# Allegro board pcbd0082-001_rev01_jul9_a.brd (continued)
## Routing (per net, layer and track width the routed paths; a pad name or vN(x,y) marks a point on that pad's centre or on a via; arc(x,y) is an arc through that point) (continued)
MUX_NFP_PCIE0_WAKE_L: length 53
  TOP w0.132: U1.AE28 v2(45.9,49.28)
  TOP w0.147: U20.13 25.26,56.53 25.01,56.79 24.63,56.79 24.37,57.05 24.37,57.33 R384.2
  07_SIG w0.121: v2(45.9,49.28) 46.42,49.81 54.98,49.81 55.36,50.19 55.36,53.39 55.07,53.69 52.75,53.69 50.41,56.03 50.41,56.78 50.1,57.09 50.1,58.63 49.01,59.71 41.9,59.71 39.87,57.68 35.04,57.68 v7(34.15,56.79)
  08_SIG w0.121: v4(24.12,57.43) 24.63,56.92 27.8,56.92 28.57,57.69 33.25,57.69 v7(34.15,56.79)
MUX_NFP_SMBUS_ALERT_L: length 34.5
  TOP w0.132: U1.AD30 v2(43.9,48.28)
  TOP w0.147: U20.3 24.75,53.68 24.75,53.11 24.63,52.98 24.37,52.98 24.27,52.88 R381.2
  04_SIG w0.121: v8(43.9,56.28) 43.3,55.69 41.73,55.69 41.31,55.27 41.24,55.27 41.17,55.19 34.19,55.19 32.02,53.02 29.81,53.02 29.17,53.67 28.73,53.67 28.24,53.18 27.87,53.18 27.38,53.67 25.18,53.67 24.24,52.72 24.24,52.65 24.12,52.53 v4(24.12,52.47)
  08_SIG w0.121: v2(43.9,48.28) 43.9,48.89 44.7,49.69 44.95,49.69 45.3,50.04 45.3,52.31 44.5,53.12 44.5,53.26 44.07,53.69 43.86,53.69 43.42,54.13 43.42,55.78 43.9,56.25 v8(43.9,56.28)
MUX_NFP_SMBUS_SCL: length 51.8
  TOP w0.132: U1.AD29 v2(44.9,48.28)
  TOP w0.147: R383.2 26.76,57.07 U20.10
  03_SIG w0.121: v4(26.28,57.43) 26.75,57.93 45.11,57.93 45.24,58.06 50.47,58.06 v5(50.6,57.93)
  07_SIG w0.121: v2(44.9,48.28) 45.41,48.79 55.99,48.79 56.38,49.17 56.38,53.62 56.11,53.88 55.61,53.88 55.3,54.19 55.3,54.45 55.07,54.69 54.93,54.69 54.72,54.89 54.72,55.52 54.47,55.78 51.8,55.78 50.6,56.98 v5(50.6,57.93)
MUX_NFP_SMBUS_SDA: length 30.3
  TOP w0.132: U1.AE29 v2(44.9,49.28)
  TOP w0.147: v4(26.25,52.47) 26.26,52.49 U20.6
  04_SIG w0.121: v8(44.9,55.28) 44.38,54.76 41.52,54.76 41.39,54.89 40.96,54.89 40.94,54.9 37.9,54.9 37.89,54.89 37.07,54.89 36.94,54.76 34.11,54.76 32.13,52.77 31.66,52.77 31.38,52.5 28.92,52.5 28.49,52.93 27.77,52.93 27.71,52.98 26.76,52.98 v4(26.25,52.47)
  08_SIG w0.121: v8(44.9,55.28) 44.9,55.22 44.44,54.76 44.44,54.17 44.93,53.69 45.07,53.69 45.5,53.26 45.5,53.12 45.73,52.88 45.87,52.88 46.34,52.41 46.34,50.16 45.87,49.69 45.58,49.69 45.18,49.28 v2(44.9,49.28)
NFP_ARM_SPI_FLASH_MISO: length 41.9
  TOP w0.132: U1.P29 v2(44.9,37.28)
  TOP w0.147: v1(29.07,43.84) 28.6,43.37 28.6,43.04 28.13,42.57 28.13,41.2 27.93,41 27.93,39.14 27.17,38.38 26.02,38.38 v5(25.13,37.49) 24.68,37.03 U15.2
  07_SIG w0.121: v2(44.9,37.28) 44.44,37.74 44.44,38.5 44.18,38.76 43.68,38.76 43.42,39.01 43.42,39.27 43.3,39.39 43.3,39.45 43.07,39.69 41.43,39.69 40.76,39.02 40.17,39.02 40.16,39.01 33.39,39.01 33.07,38.7 33.07,38.44 32.75,38.12 31.64,38.12 31.34,37.82 31.34,37.56 31.11,37.33 29.87,37.33 29.71,37.49 28.69,37.49 27.8,36.6 26.53,36.6 25.64,37.49 v5(25.13,37.49)
  BOTTOM w0.147: v5(25.13,37.49) 25.13,40.58 25.26,40.71 25.26,41.39 R20.2
NFP_ARM_SPI_FLASH_MOSI: length 24.4
  TOP w0.147: U15.5 v4(27.22,40.66) 27.37,40.95 27.67,41.25 R23.2
  04_SIG w0.121: v3(40.72,40.41) 39.48,40.41 38.98,39.9 37.07,39.9 36.56,39.39 35.8,39.39 35.17,40.03 32.88,40.03 32.12,40.79 27.34,40.79 27.22,40.67 v4(27.22,40.66)
  BOTTOM w0.147: U7.5 27.67,36.35 27.04,36.98 27.04,40.52 27.19,40.66 v4(27.22,40.66) 27.22,40.71 v1(27.8,41.3)
NFP_ARM_SPI_FLASH_SCK: length 29.6
  TOP w0.147: U15.6 v4(25.95,40.66) 26.4,41.12 R22.2
  04_SIG w0.121: v4(25.95,40.66) 26.83,39.77 31.1,39.77 31.36,39.52 34.91,39.52 35.51,38.92 38.6,38.92 39.01,38.51 39.01,37.71 39.36,37.36 39.83,37.36 v3(40.33,36.85)
  BOTTOM w0.147: v4(25.95,40.66) 25.77,40.49 25.77,36.6 26.4,35.96 26.4,32.32 27.03,31.7 27.62,31.7 28.51,30.81 v1(28.55,30.81)
NFP_ARM_SPI_FLASH_SEL: length 46.1
  TOP w0.147: v1(21.32,36.47) 21.83,36.47 22.09,36.22 22.09,33.57 22.23,33.42 23.1,33.42 23.41,33.12 U15.1 23.41,32.1 23.86,31.65 v4(23.86,31.1)
  04_SIG w0.121: v2(41.9,42.28) 41.93,42.28 42.5,41.72 42.5,38.85 41.89,38.24 41.76,38.24 40.87,37.35 40.17,37.35 39.48,38.04 39.48,38.63 38.98,39.14 38.7,39.14 38.7,39.15 35.67,39.15 35.04,39.77 31.74,39.77 31.1,40.41 27.67,40.41 27.42,40.16 27.08,40.16 26.04,41.19 25.79,41.19 25.13,40.54 25.13,40.28 24.63,39.77 24.63,38.25 v5(23.86,37.49)
  BOTTOM w0.147: R32.1 v5(23.86,37.49) 23.86,36.6 24.5,35.96 24.5,31.27 24.37,31.14 23.9,31.14 v4(23.86,31.1)
NFP_ARM_SPI_FLASH_WP_L: length 35
  TOP w0.132: U1.AA29 v8(44.9,45.28)
  TOP w0.147: v5(26.4,37.49) 25.95,37.03 U15.3
  03_SIG w0.121: v8(44.9,45.28) 44.21,45.28 43.3,46.19 43.3,46.45 42.99,46.76 42.66,46.76 42.3,46.4 42.3,46.02 42.02,45.74 38.89,45.74 37.58,47.05 34.95,47.05 33.01,45.11 33.01,43.71 32.5,43.2 31.99,43.2 26.4,37.62 v5(26.4,37.49)
  BOTTOM w0.147: R29.2 v5(26.4,37.49)
NFP_CFG_SPI_FLASH_HOLD_L: length 68.2
  TOP w0.147: v3(33.06,34.36) 32.65,34.78 U2.K12
  07_SIG w0.121: v4(27.29,14.06) 27.63,14.39 27.63,14.64 28.17,15.18 29.33,15.18 30.66,13.85 30.66,13.62 30.92,13.36 32.45,13.36 32.75,13.06 33.86,13.06 34.35,13.55 34.71,13.55 35.13,13.13 37.49,13.13 37.88,12.74 38.38,12.74 38.98,12.15 40.43,12.15 41.31,11.27 42.42,11.27 42.8,11.65 44.24,11.65 44.5,11.91 44.5,13.55 v4(44.06,13.99)
  08_SIG w0.121: v4(27.29,14.06) 27.17,14.18 27.17,17.99 30.03,20.85 30.03,21.56 29.9,21.69 29.9,22.05 30.03,22.18 30.03,25.24 31.92,27.14 31.92,27.77 33,28.84 33,29.24 33.01,29.25 33.01,32.54 32.63,32.92 32.63,33.81 33.06,34.24 v3(33.06,34.36) 32.7,34.36 32.37,34.69 32.37,36.85 33.02,37.5 33.02,37.88 32.73,38.16 32.46,38.16 32.23,38.39 32.23,38.77 29.71,41.3 29.71,45.74 28.94,46.51 28.31,46.51 27.8,46 27.29,46 26.66,46.63 26.66,46.89 25.39,48.16 v4(25.39,49.55)
  BOTTOM w0.147: R25.2 v4(25.39,49.55)
NFP_CFG_SPI_FLASH_MISO: length 26.2
  TOP w0.132: U1.V30 v2(43.9,42.28)
  TOP w0.147: U8.2 25.39,43.84 v7(25.77,43.46)
  04_SIG w0.121: v2(43.9,42.28) 43.3,42.88 40.94,42.88 40.56,43.26 40.56,43.26 40.3,43.52 40.3,43.52 40.17,43.65 39.94,43.65 39.68,43.91 39.68,45.04 37.58,47.14 34.79,47.14 31.74,44.09 26.4,44.09 v7(25.77,43.46)
  BOTTOM w0.147: v7(25.77,43.46) 25.77,44.09 25.51,44.35 R24.2
NFP_CFG_SPI_FLASH_MOSI: length 30.6
  04_SIG w0.121: v3(40.33,39.52) 40.87,39.52 40.99,39.64 40.99,39.66 41.39,40.05 41.39,40.68 40.99,41.07 39.13,41.07 38.6,40.54 36.55,40.54 36.49,40.6 36.13,40.6 36.07,40.54 33.52,40.54 32.5,41.55 27.17,41.55 26.78,41.93 26.18,41.93 24.94,43.17 24.94,43.78 24.5,44.22 24.5,46.36 24.38,46.47 24.38,47.3 24.97,47.89 24.99,47.89 26.02,48.92 26.02,49.68 26.4,50.06 27.42,50.06 v4(27.93,49.55)
  BOTTOM w0.147: R27.2 v4(27.93,49.55)
NFP_CFG_SPI_FLASH_SCK: length 30
  04_SIG w0.121: v4(26.66,49.55) 26.66,48.66 25.38,47.39 25.18,47.39 24.89,47.09 24.89,46.68 25.01,46.56 25.01,45.87 25.26,45.62 25.26,43.33 25.77,42.82 32.75,42.82 34.54,41.04 35.5,41.04 35.61,40.93 37.01,40.93 37.12,41.04 37.93,41.04 37.96,41.04 38.6,41.68 41.01,41.68 41.11,41.58 41.2,41.58 41.48,41.29 41.48,41.11 41.64,40.96 41.64,39.59 41.5,39.45 41.5,39.3 41.37,39.17 41.37,38.78 v3(40.33,37.74)
  BOTTOM w0.147: R26.2 v4(26.66,49.55)
NFP_CFG_SPI_FLASH_SEL: length 28.5
  TOP w0.147: U8.1 24.12,43.84 v5(24.5,43.46) 24.24,43.2 v1(22.72,43.2)
  04_SIG w0.121: v3(40.33,38.63) 39.87,39.1 39.87,39.77 40,39.91 40.81,39.91 41.13,40.24 41.13,40.58 40.89,40.83 39.52,40.83 38.85,40.16 36.94,40.16 36.5,39.71 35.83,39.71 35.27,40.28 33.27,40.28 32.37,41.17 26.94,41.17 26.56,41.55 25.31,41.55 24.5,42.36 v5(24.5,43.46)
  BOTTOM w0.147: v5(24.5,43.46) R30.2 R18.1
NFP_CFG_SPI_FLASH_WP_L: length 23.7
  TOP w0.127: v3(29.27,34.49) 29.72,34.91 30.26,34.91 30.39,34.78 U2.K14
  TOP w0.147: v7(27.93,43.33) 27.04,43.33 26.66,43.71 U8.3
  07_SIG w0.121: v7(27.93,43.33) 28.18,43.08 28.18,41 25.93,38.76 24.5,38.76 23.36,37.62 23.36,37.23 26.1,34.49 v3(29.27,34.49)
  BOTTOM w0.147: R31.2 26.66,43.71 27.04,43.33 v7(27.93,43.33)
NFP_CLK_NRESET_L: length 19.8
  TOP w0.132: U1.M28 v2(45.9,35.28)
  TOP w0.147: v3(29.2,37.02) v1(29.2,37.87)
  07_SIG w0.121: v3(29.2,37.02) 29.49,36.73 31.99,36.73 32.75,35.96 38.72,35.96 39.22,35.47 41.02,35.47 41.39,35.84 43.04,35.84 43.5,35.38 43.5,35.12 43.79,34.82 45.44,34.82 v2(45.9,35.28)
NFP_CLK_NRESET_OUT_L: length 6.9
  TOP w0.127: v3(40.25,34.95) 39.7,34.4 38.42,34.4 38.3,34.28 U2.J1
  TOP w0.132: U1.M31 v2(42.9,35.28)
  07_SIG w0.121: v2(42.9,35.28) 42.44,34.82 40.37,34.82 v3(40.25,34.95)
  BOTTOM w0.147: R19.2 43.4,34.78 v2(42.9,35.28)
NFP_CLK_REF_N: length 25.1
  TOP w0.099: U1.T27 v2(46.9,39.28) ; R135.2 v7(40.25,49.05)
  03_SIG w0.096: v7(40.25,49.05) 40.25,49.45 40.54,49.74 41.19,49.74 41.25,49.67 41.65,49.67 42.06,49.67 42.06,49.67 42.42,49.67 43.41,48.67 44.06,48.67 44.29,48.44 44.29,47.92 44.53,47.67 47.06,47.67 47.29,47.44 47.29,46.44 47.29,46.44 47.29,46.03 47.65,45.67 48.06,45.67 48.29,45.44 48.29,45.03 48.65,44.68 49.5,44.68 50.29,43.89 50.29,39.12 50.06,38.89 47,38.89 46.9,38.99 v2(46.9,39.28)
  BOTTOM w0.099: v2(46.9,39.28) U1.T27
NFP_CLK_REF_P: length 25.2
  TOP w0.099: R134.2 v7(40.25,50.19) ; U1.R27 v2(46.9,38.28)
  03_SIG w0.096: v2(46.9,38.28) 47.29,38.68 50.15,38.68 50.5,39.03 50.5,43.98 49.59,44.89 48.74,44.89 48.51,45.12 48.51,45.53 48.15,45.89 47.74,45.89 47.51,46.12 47.51,46.53 47.5,46.53 47.5,47.53 47.15,47.89 44.62,47.89 44.5,48.01 44.5,48.53 44.15,48.89 43.5,48.89 42.5,49.89 42.15,49.89 41.34,49.89 41.28,49.95 41.17,49.95 41.13,50 40.44,50 v7(40.25,50.19)
  BOTTOM w0.099: v2(46.9,38.28) U1.R27
NFP_CORE_PWM1: length 44.2
  TOP w0.147: U10.29 37.66,22.47 38.21,23.03 v7(38.21,23.01)
  07_SIG w0.121: v5(67.86,21.11) 68.1,20.87 70.49,20.87 71.23,21.61 71.23,22.38 71.36,22.5 71.36,25.55 71.11,25.8 47.61,25.8 46.22,24.41 45.2,24.41 44.44,23.65 42.91,23.65 42.66,23.39 38.6,23.39 v7(38.21,23.01)
  BOTTOM w0.203: U6.40 68.03,20.98 67.91,21.11 v5(67.86,21.11)
NFP_CORE_PWM2: length 15.4
  TOP w0.147: U10.28 37.69,21.97 37.71,21.99 v7(38.07,21.99)
  04_SIG w0.121: v5(48.26,21.11) 47.12,19.96 46.09,19.96 45.45,20.6 43.93,20.6 43.6,20.27 39.03,20.27 38.72,19.96 37.83,19.96 37.58,20.22 37.58,20.99 38.07,21.49 v7(38.07,21.99)
  BOTTOM w0.203: U5.40 48.44,20.98 48.31,21.11 v5(48.26,21.11)
NFP_CORE_VID0: length 54.3
  TOP w0.132: U1.AJ31 v8(42.9,53.28)
  08_SIG w0.121: v8(42.9,53.28) 42.41,53.78 42.41,54.38 42.15,54.63 42.12,54.63 42.07,54.69 40.56,54.69 38.98,53.1 38.46,53.1 37.96,52.6 37.96,52.08 37.59,51.71 37.59,51.66 34.15,48.22 32.31,48.22 31.61,48.92 31,48.92 30.05,47.97 27.35,47.97 26.22,49.11 26.22,50 25.7,50.51 24.94,50.51 24.56,50.12 24.56,46.06 25.01,45.62 25.01,42.85 24.63,42.47 24.63,41.55 25.13,41.04 25.13,40.66 27.57,38.22 30.25,38.22 30.48,37.99 30.48,37.35 31.37,36.46 31.37,28.99 31.34,28.97 31.34,28.92 29.75,27.33 v5(29.71,27.33)
  BOTTOM w0.147: v5(29.71,27.33) R179.1
NFP_CORE_VID1: length 54.2
  TOP w0.132: U1.AG31 v8(42.9,51.28)
  08_SIG w0.121: v5(31.48,27.33) 31.48,28.09 32.15,28.76 32.15,29.45 31.61,30 31.61,36.6 31.36,36.85 31.36,37.95 30.8,38.5 27.8,38.5 26.4,39.9 26.4,41.04 25.64,41.81 25.64,42.57 25.33,42.88 25.33,43.64 25.39,43.7 25.39,46.25 24.95,46.69 24.95,49.87 25.13,50.06 25.5,50.06 25.9,49.67 25.9,48.79 27.42,47.27 27.68,47.27 28,46.95 28.5,46.95 29.2,47.65 29.64,47.65 29.71,47.72 30.16,47.72 30.34,47.9 34.66,47.9 36.06,49.3 36.06,49.43 38.6,51.97 39.1,51.97 40.88,53.74 42.01,53.74 42.41,53.35 42.41,53.11 42.66,52.86 42.9,52.86 43.3,52.45 43.3,51.69 v8(42.9,51.28)
  BOTTOM w0.147: R176.1 v5(31.48,27.33)
NFP_CORE_VID2: length 35.7
  TOP w0.132: U1.AH32 v2(41.9,52.28)
  08_SIG w0.121: v6(33.26,27.58) 33.26,28.34 33.78,28.86 33.78,29.37 34.92,30.51 34.92,33.03 34.74,33.21 34.52,33.21 34.26,33.47 34.26,34.53 34,34.79 33.71,34.79 33.45,35.04 33.45,36.15 34.72,37.43 34.72,38.95 31.99,41.68 31.99,44.73 37.96,50.7 38.98,50.7 39.23,50.95 39.23,51.33 39.93,52.03 41.65,52.03 v2(41.9,52.28)
  BOTTOM w0.147: v6(33.26,27.58) 32.83,27.15 32.83,27.06 R172.1
NFP_CORE_VID3: length 37.1
  TOP w0.132: U1.AJ32 v8(41.9,53.28)
  08_SIG w0.121: v5(34.15,27.33) 33.81,27.67 33.81,28.44 34.05,28.68 34.38,28.68 34.65,28.95 34.65,29.35 35.8,30.5 35.8,31.85 35.8,31.85 35.8,32.16 35.41,32.55 35.41,33.05 35.07,33.39 35.07,33.77 34.66,34.19 34.66,34.65 34.28,35.03 34.28,36.22 35.55,37.49 35.55,38.36 35.54,38.37 35.54,38.9 32.88,41.55 32.88,43.85 32.94,43.91 32.94,45.16 36.13,48.34 36.63,48.34 37.97,49.68 39.23,49.68 39.68,50.13 39.68,51.39 40.08,51.79 41.97,51.79 42.06,51.88 42.07,51.88 42.3,52.12 42.3,52.12 42.41,52.22 42.41,52.47 41.9,52.98 v8(41.9,53.28)
  BOTTOM w0.147: R175.1 v5(34.15,27.33)
NFP_CORE_VID4: length 30.4
  TOP w0.132: U1.AG32 v2(41.9,51.28)
  08_SIG w0.121: v2(41.9,51.28) 41.59,51.28 40.69,50.38 40.69,50.01 40.43,49.75 40.19,49.75 39.36,48.92 39.36,44.35 39.37,44.29 39.37,43.69 39.36,43.63 39.36,42.57 36.35,39.56 36.35,38.37 36.43,38.29 36.43,37.48 35.07,36.13 35.07,34.23 35.33,33.97 35.63,33.97 35.89,33.71 35.89,33.21 36.58,32.52 36.58,31.41 36.44,31.27 36.44,30.25 35.46,29.27 35.46,28.92 35.93,28.45 v6(35.93,27.58)
  BOTTOM w0.147: v6(35.93,27.58) 35.49,27.15 35.49,27.06 R174.1
NFP_CORE_VID5: length 30.7
  TOP w0.132: U1.AH31 v8(42.9,52.28)
  08_SIG w0.121: v5(36.82,27.33) 36.27,27.87 36.27,29.32 36.82,29.87 36.82,33.68 36.56,33.93 36.17,33.93 35.92,34.19 35.92,35.45 37.21,36.74 37.21,38.32 37.16,38.37 37.16,39.87 39.68,42.38 39.68,47.96 40.06,48.34 40.18,48.34 40.94,49.1 40.94,50.12 41.64,50.82 42.02,50.82 42.5,51.3 42.5,51.88 v8(42.9,52.28)
  BOTTOM w0.147: R177.1 v5(36.82,27.33)
NFP_CORE_VID6: length 27.2
  TOP w0.132: U1.AF32 v2(41.9,50.28)
  08_SIG w0.121: v2(41.9,50.28) 41.39,49.77 41.39,48.69 41.25,48.55 41.25,41.55 39.87,40.17 39.87,36.58 39.6,36.31 39.07,36.31 38.21,35.46 38.21,35.33 37.89,35.01 37.89,30.06 38.79,29.17 38.79,28.28 38.6,28.09 v7(38.6,27.58)
  BOTTOM w0.147: v7(38.6,27.58) 38.16,27.15 38.16,27.14 37.83,26.81 37.83,26.73 R173.1
NFP_CORE_VID7: length 31.2
  TOP w0.132: U1.AG30 v2(43.9,51.28)
  08_SIG w0.121: v2(43.9,51.28) 43.9,50.54 42.05,48.69 41.73,48.69 41.5,48.45 41.5,40.52 40.75,39.77 40.75,39.77 40.75,39.76 40.75,36.25 39.83,35.33 39.83,34.56 40.72,33.66 41.07,33.66 41.52,33.22 41.52,26.95 41.01,26.44 41.01,26.27 v4(40.28,25.55)
  BOTTOM w0.147: v4(40.28,25.55) 40.28,24.88 v1(40.88,24.28)
NFP_CPLD_INT_L: length 39.5
  TOP w0.127: U2.L14 30.94,35.75 29.69,35.75 v3(29.27,35.33)
  TOP w0.132: U1.AA28 v2(45.9,45.28)
  TOP w0.147: v1(30.47,42.82) 30.21,42.57 30.21,40.79 29.83,40.41 29.2,40.41 28.58,39.8 28.58,38.01 28.56,37.99 28.56,35.58 28.82,35.33 v3(29.27,35.33)
  03_SIG w0.105: 47.49,43.41 47.06,43.84 46.6,43.84 46.5,43.93 46.5,44.53 45.9,45.13 v2(45.9,45.28)
  03_SIG w0.121: v3(29.27,35.33) 29.27,35.91 29.96,36.6 30.34,36.6 30.59,36.85 37.41,36.85 38.46,37.91 38.76,37.91 38.99,38.13 40.39,38.13 40.73,38.47 40.73,38.68 42.71,40.66 44.95,40.66 45.5,41.21 45.5,41.45 45.73,41.69 45.97,41.69 46.5,42.21 46.5,42.45 46.73,42.69 46.97,42.69 47.49,43.2 47.49,43.41
  BOTTOM w0.127: v3(29.27,35.33) 29.69,34.91 30.26,34.91 30.35,34.82 R58.1
NFP_CPLD_PRGM_JTAG_TCK: length 38.4
  TOP w0.132: U1.AD28 v2(45.9,48.28)
  TOP w0.147: U12.3 26.52,27.85 26.4,27.96 v4(26.4,29.07)
  04_SIG w0.121: v4(26.4,29.07) 27.71,30.38 29.45,30.38 29.87,30.79 34.19,30.79 34.92,31.53 34.92,32.42 35.92,33.42 35.92,35.29 36.34,35.71 36.69,35.71 37.07,36.09 38.56,36.09 39.04,36.57 39.04,36.86 39.29,37.11 39.58,37.11 39.82,36.86 39.82,36.81 40.17,36.46 41.25,36.46 41.52,36.73 43.04,36.73 43.42,37.11 43.42,38.23 43.5,38.31 43.5,41.45 43.93,41.88 44.07,41.88 44.31,42.12 44.31,42.31 44.87,42.88 45.07,42.88 45.45,43.27 45.45,45.41 45.93,45.88 46.22,45.88 46.47,46.12 46.47,47.71 v2(45.9,48.28)
NFP_CPLD_PRGM_JTAG_TDI: length 51.1
  TOP w0.132: U1.AC27 v2(46.9,47.28)
  TOP w0.147: v4(22.63,30.38) 22.63,30.82 22.21,31.24 v1(22.21,31.77) 22.8,31.77 23.36,31.22 23.36,30.97 23.66,30.66 23.66,28.67 24.37,27.96 24.75,27.96 25.02,27.7 U12.6
  04_SIG w0.121: v2(46.9,47.28) 47.36,46.82 47.36,43.08 46.97,42.69 46.73,42.69 46.5,42.45 46.5,42.31 46.07,41.88 45.93,41.88 45.45,41.41 45.45,35.2 45.07,34.82 41.77,34.82 41.26,35.33 41.26,35.34 41.14,35.46 39.58,35.46 39.57,35.47 38.43,35.47 38.42,35.46 37.45,35.46 37.07,35.08 37.07,31.77 34.79,29.49 29.83,29.49 28.94,28.6 23.74,28.6 23.48,28.85 23.48,29.53 v4(22.63,30.38)
NFP_CPLD_PRGM_JTAG_TDO: length 48.9
  TOP w0.132: U1.AC28 v2(45.9,47.28)
  TOP w0.147: R67.2 v4(24.27,23.58) 24.52,23.83 U12.10
  03_SIG w0.121: v2(45.9,47.28) 46.34,46.84 46.34,46.25 46.91,45.69 47.07,45.69 47.3,45.45 47.3,45.29 47.91,44.69 48.07,44.69 48.3,44.45 48.3,44.29 48.88,43.71 49.14,43.71 49.39,43.46 49.39,43.2 49.07,42.88 48.73,42.88 48.3,42.45 48.3,42.12 48.07,41.88 47.73,41.88 47.3,41.45 47.3,41.12 47.07,40.88 46.73,40.88 45.67,39.81 43.84,39.81 43.3,39.28 43.3,39.12 42.87,38.69 42.73,38.69 41.5,37.45 41.5,37.34 40.43,36.28 38.28,36.28 38.09,36.09 31.46,36.09 30.25,34.88 29.92,34.88 29.66,34.62 29.66,34.33 29.44,34.1 28.27,34.1 v5(27.04,35.33)
  08_SIG w0.121: v4(24.27,23.58) 24.24,24.41 23.86,24.79 23.86,28.34 23.61,28.6 23.61,29.23 23.87,29.49 24.3,29.49 25.26,30.45 25.26,30.66 26.02,31.42 26.02,34.31 v5(27.04,35.33)
NFP_CPLD_PRGM_JTAG_TMS: length 48.7
  TOP w0.132: U1.AC30 v2(43.9,47.28)
  TOP w0.147: R66.2 26.44,24.03 26.28,24.03 26.02,24.28 U12.13
  03_SIG w0.121: v7(28.18,32.03) 28.18,32.15 26.6,33.74 26.6,35.51 26.86,35.77 27.87,35.77 28.75,34.88 29.39,34.88 29.69,35.19 29.69,35.49 29.92,35.72 30.22,35.72 30.98,36.47 37.71,36.47 38.34,37.11 40.04,37.11 40.17,37.25 40.51,37.25 42.41,39.14 42.41,39.52 43.17,40.28 45.58,40.28 46.5,41.2 46.5,41.45 46.73,41.69 46.98,41.69 47.5,42.2 47.5,42.45 47.73,42.69 47.98,42.69 48.37,43.08 48.37,43.46 47.95,43.88 47.73,43.88 47.5,44.12 47.5,44.26 47.07,44.69 46.93,44.69 46.5,45.12 46.5,45.26 46.01,45.74 45.71,45.74 45.45,46 45.45,46.51 45.2,46.76 44.42,46.76 v2(43.9,47.28)
  07_SIG w0.121: v4(26.91,23.58) 26.91,29.84 27.03,29.96 28.18,31.11 v7(28.18,32.03)
NFP_FAIL_SAFE_BOOT_L: length 84.7
  TOP w0.127: v3(33.87,34.36) 33.45,34.78 33.45,35.35 33.41,35.39 U2.M10
  TOP w0.132: U1.AB30 v2(43.9,46.28)
  TOP w0.147: v5(22.34,32.79) 22.12,32.57 R34.1
  07_SIG w0.121: v2(43.9,46.28) 43.42,46.76 37.96,46.76 37.58,47.14 34.66,47.14 31.23,43.71 31.23,42.82 26.46,38.05 25.08,38.05 24.69,37.67 24.69,37.1 24.81,36.98 25.51,36.98 26.66,35.84 27.15,35.84 27.27,35.72 30.25,35.72 30.39,35.58 34.83,35.58 35.07,35.34 35.07,35.04 35.36,34.76 35.66,34.76 35.89,34.53 35.89,34.2 35.63,33.94 34.9,33.94 34.48,34.36 v3(33.87,34.36) 33.61,34.36 33.22,33.97 32.9,33.97 32.82,34.05 28.8,34.05 27.42,32.66 22.47,32.66 v5(22.34,32.79)
  08_SIG w0.121: v5(22.34,32.79) 22.09,32.54 22.09,29.74 22.19,29.64 22.19,23.92 23.8,22.32 23.8,22.26 23.86,22.2 23.86,21.79 23.56,21.49 23.11,21.49 20.94,19.33 20.94,16.28 20.31,15.64 20.31,12.09 20.94,11.45 v4(20.94,10.12)
  BOTTOM w0.102: TP17.1 32.52,33.96 33.46,33.96 v3(33.87,34.36)
  BOTTOM w0.147: v2(43.9,46.28) R16.1
NFP_JTAG_ARM_TCK: length 75.3
  TOP w0.132: U1.AA31 v2(42.9,45.28)
  07_SIG w0.121: v7(44.06,15.26) 45.2,14.12 45.2,11.9 44.45,11.15 43.01,11.15 42.57,10.7 40.68,10.7 40.36,11.02 40.26,11.13 39.2,11.13 38.99,11.34 37.85,11.34 37.13,12.06 36.47,12.06 v4(36.44,12.09) 36.43,12.09 36.39,12.13 35.59,12.13 35.37,11.91 32.49,11.91 32.04,12.37 29.76,12.37 28.77,13.36 28.36,13.36 28.06,13.06 28.06,12.7 26.67,11.31 25.42,11.31 25.14,11.03 16.47,11.03 v4(14.59,12.91)
  08_SIG w0.121: v7(44.06,15.26) 43.8,15.52 43.8,21.11 44.44,21.74 44.44,30.74 v2(43.9,31.28) 44.44,31.77 44.44,39.9 45.45,40.92 45.45,43.3 45.07,43.69 44.93,43.69 44.5,44.12 44.5,44.29 43.5,45.28 v2(42.9,45.28)
  BOTTOM w0.147: v4(14.59,12.91) 14.66,12.98 14.97,12.98 15.86,13.87 J5.5 ; R408.1 43.9,30.51 v2(43.9,31.28)
NFP_JTAG_ARM_TDI: length 86.1
  TOP w0.132: U1.Y32 v2(41.9,44.28)
  04_SIG w0.121: v5(28.18,47.39) 30.09,45.49 32.28,45.49 34.5,47.71 34.59,47.71 35.17,48.29 36.07,48.29 36.13,48.34 36.49,48.34 36.55,48.29 37.13,48.29 40.17,45.25 40.17,45.15 40.97,44.35 41.38,44.35 41.45,44.28 v2(41.9,44.28)
  07_SIG w0.121: v4(38.34,12.09) 37.94,12.49 37.78,12.49 37.39,12.88 35.28,12.88 35.06,12.66 32.8,12.66 32.35,13.11 30.82,13.11 30.31,13.62 29.65,13.62 29.25,14.01 29.25,14.53 28.85,14.94 28.28,14.94 27.87,14.53 27.87,13.99 27.31,13.43 27.31,13.01 26.36,12.06 25.11,12.06 24.89,11.83 22.09,11.83 22.05,11.82 21.87,11.78 18.38,11.78 17.89,12.27 17.89,12.78 17.31,13.36 16.3,13.36 v4(15.86,12.91)
  08_SIG w0.121: v4(38.34,12.09) 39.03,12.78 39.03,13.9 38.85,14.08 38.85,14.12 38.47,14.5 38.47,15.97 38.53,16.03 38.53,16.4 38.47,16.46 38.47,17.68 40.05,19.25 40.09,19.25 40.34,19.51 40.34,19.55 40.83,20.04 40.83,23.32 40.5,23.65 40.5,24.92 40.83,25.24 40.83,25.57 41.39,26.13 41.39,26.44 41.77,26.82 41.77,33.33 41.64,33.46 41.64,33.58 41.31,33.91 40.83,33.91 40.57,34.17 40.57,34.53 40.88,34.85 40.88,34.88 40.99,34.99 40.99,39.66 41.31,39.97 41.31,39.98 41.74,40.41 41.74,40.51 42.41,41.17 42.41,43.46 41.9,43.96 v2(41.9,44.28)
  BOTTOM w0.147: J5.7 17.13,13.87 16.24,12.98 15.93,12.98 v4(15.86,12.91) ; R403.2 27.46,47.39 v5(28.18,47.39) 29.1,47.39 R147.1
NFP_JTAG_ARM_TDO: length 83
  TOP w0.147: v5(28.69,44.73) 28.82,44.85 R263.2
  07_SIG w0.121: v5(28.69,44.73) 28.69,44.6 27.86,43.77 27.74,43.77 27.04,43.07 27.04,41.3 26.66,40.92 26.66,40.16 25.64,39.14 24.37,39.14 23.52,38.29 23.52,38.17 23.03,37.69 23.03,36.29 23.36,35.96 23.36,34.44 23.16,34.25 23.16,34 22.9,33.75 21.9,33.75 20.94,32.79 20.94,31.39 19.04,29.49 v5(14.72,29.49) ; v4(17.13,12.91) 17.13,12.68 18.28,11.53 24.94,11.53 25.22,11.81 26.47,11.81 27.56,12.91 27.56,13.33 28.12,13.89 28.12,14.43 28.38,14.69 28.74,14.69 29,14.43 29,13.91 29.55,13.37 30.21,13.37 30.71,12.87 32.24,12.87 32.69,12.42 35.17,12.42 35.38,12.63 37.17,12.63 38.16,11.65 38.52,11.65 38.58,11.71 v4(40.25,11.71)
  08_SIG w0.121: v4(17.13,12.91) 12.94,17.11 12.94,21.23 13.45,21.74 13.45,26.19 14.34,27.07 14.34,29.11 v5(14.72,29.49)
  BOTTOM w0.147: v5(28.69,44.73) 29.2,45.24 R147.2 29.95,46.65 30.39,47.09 30.39,48.68 30.59,48.88 30.59,50.06 30.34,50.32 R404.2 ; v4(17.13,12.91) 17.32,13.1 17.64,13.1 18.4,13.87 J5.9
NFP_JTAG_ARM_TMS: length 74.5
  TOP w0.132: U1.AA32 v2(41.9,45.28)
  07_SIG w0.121: v4(42.15,11.71) 41.37,12.49 39.38,12.49 38.7,13.17 38.16,13.17 37.15,14.18 34.95,14.18 34.81,14.05 34.14,14.05 34.02,13.93 31.76,13.93 30,15.69 27.97,15.69 27.12,14.84 27.12,14.6 26.79,14.27 26.79,13.85 25.5,12.56 25.02,12.56 24.8,12.34 21.99,12.34 21.98,12.33 21.9,12.3 21.82,12.28 18.59,12.28 18.4,12.47 v4(18.4,12.91)
  08_SIG w0.121: v2(41.9,45.28) 41.98,45.28 42.41,44.85 42.41,44.09 42.81,43.69 43.07,43.69 43.3,43.45 43.3,41.12 42.16,39.97 42.02,39.97 41.5,39.45 41.5,35.1 42.15,34.44 42.15,28.73 42.53,28.34 42.53,26.19 42.15,25.8 41.77,25.8 41.33,25.36 41.33,16.9 41.9,16.33 41.9,11.96 v4(42.15,11.71)
  BOTTOM w0.147: J5.11 19.67,13.61 19.16,13.1 18.59,13.1 v4(18.4,12.91) ; R405.2 42.69,49.48 42.65,49.48 42.41,49.72 41.69,49.72 41.39,49.43 41.39,45.79 v2(41.9,45.28)
NFP_JTAG_ARM_TRST_L: length 67.2
  TOP w0.132: U1.Y31 v2(42.9,44.28)
  07_SIG w0.121: v4(22.21,12.91) 22.66,13.36 25.95,13.36 26.53,13.94 26.53,14.95 27.76,16.19 30.21,16.19 31.96,14.43 33.81,14.43 33.93,14.55 34.04,14.55 35.24,15.74 35.6,15.74 36.09,15.26 36.88,15.26 38.01,14.13 38.45,14.13 39.59,12.99 43.15,12.99 v4(44.06,12.09)
  08_SIG w0.121: v4(44.06,12.09) 42.41,13.74 42.41,25.42 43.04,26.06 43.04,28.47 42.66,28.85 42.66,28.95 42.5,29.12 42.5,29.45 42.66,29.61 42.66,31.04 v2(42.9,31.28) 42.66,31.52 42.66,32.95 42.5,33.12 42.5,39.61 43.76,40.88 44.07,40.88 44.44,41.25 44.44,43.46 44.06,43.84 43.55,43.84 43.1,44.28 v2(42.9,44.28)
  BOTTOM w0.147: R406.2 43.4,31.78 v2(42.9,31.28) R407.1 ; v4(22.21,12.91) 21.89,12.91 20.94,13.87 J5.13
NFP_PCIE0_PER0_N: length 93.3
  04_SIG w0.11: v4(66.38,58.48) 66.28,58.58 66.28,59.12 64.47,60.94 49.3,60.94 48.79,60.43 34.21,60.43 33.71,60.94 17.47,60.94 17.43,60.91 9.57,60.91 7.01,58.35 7.01,56.18 7.57,55.62 7.57,46.19 9.01,44.75 9.01,41.25 10.57,39.69 16.27,39.69 16.73,40.15 16.73,43.13 16.84,43.25 17.13,43.25 17.28,43.09 v6(17.28,42.99)
  BOTTOM w0.139: J4.83 v6(17.28,42.99)
NFP_PCIE0_PER0_P: length 93.2
  04_SIG w0.11: v4(65.38,58.48) 65.68,58.48 66.07,58.87 66.07,59.04 64.38,60.73 49.39,60.73 48.88,60.22 34.13,60.22 33.62,60.73 17.56,60.73 17.52,60.69 9.66,60.69 7.23,58.26 7.23,56.27 7.78,55.71 7.78,46.28 9.22,44.84 9.22,41.33 10.66,39.9 16.18,39.9 16.52,40.24 16.52,43.22 16.75,43.46 17.13,43.46 17.28,43.61 v13(17.28,44.26)
  BOTTOM w0.139: J4.75 v13(17.28,44.26)
NFP_PCIE0_PER1_N: length 83.4
  04_SIG w0.11: v6(16.01,40.45) 15.82,40.64 15.56,40.64 15.27,40.93 15.27,41.89 14.97,42.19 10.66,42.19 10.02,42.82 10.02,45.06 8.94,46.15 8.94,46.64 8.27,47.3 8.27,56.11 8.35,56.18 8.35,56.75 8.61,57.01 8.61,58.84 9.96,60.19 17.14,60.19 17.39,59.94 28.1,59.94 28.38,60.23 33.41,60.23 33.93,59.71 49.14,59.71 49.77,60.35 63.02,60.35 64.16,59.21 64.16,58.69 v4(64.38,58.48)
  BOTTOM w0.139: J4.100 v6(16.01,40.45)
NFP_PCIE0_PER1_P: length 83.3
  04_SIG w0.11: v4(63.49,58.48) 63.78,58.48 63.95,58.66 63.95,59.12 62.94,60.14 49.86,60.14 49.22,59.5 33.84,59.5 33.33,60.01 28.47,60.01 28.18,59.73 17.31,59.73 17.05,59.98 10.04,59.98 8.82,58.75 8.82,56.92 8.56,56.66 8.56,56.1 8.48,56.02 8.48,47.39 9.15,46.73 9.15,46.23 10.23,45.15 10.23,42.91 10.74,42.4 15.06,42.4 15.48,41.98 15.48,41.02 15.65,40.85 15.79,40.85 16.01,41.07 v13(16.01,41.72)
  BOTTOM w0.139: J4.92 v13(16.01,41.72)
NFP_PCIE0_PER2_N: length 84.2
  04_SIG w0.11: v4(61.55,58.48) 61.94,58.87 61.94,59.36 61.65,59.65 60.89,59.65 60.83,59.59 50.53,59.59 49.73,58.79 33.54,58.79 33.03,59.3 28.77,59.3 28.23,58.76 19.09,58.76 18.84,59.01 17.01,59.01 16.76,59.27 11.02,59.27 9.98,58.23 9.98,57.09 9.26,56.37 9.26,48.02 11.02,46.27 11.25,46.27 11.63,45.89 11.63,45.2 11.89,44.94 17.6,44.94 18.11,44.43 18.11,39.61 17.5,39 17.5,38.39 17.98,37.91 v6(18.55,37.91)
  BOTTOM w0.139: J4.115 v6(18.55,37.91)
NFP_PCIE0_PER2_P: length 84.2
  04_SIG w0.11: v13(17.28,37.91) 17.28,39.08 17.9,39.7 17.9,44.34 17.51,44.73 11.8,44.73 11.42,45.11 11.42,45.8 11.16,46.06 10.93,46.06 9.05,47.94 9.05,56.46 9.77,57.17 9.77,58.32 10.93,59.48 16.84,59.48 17.1,59.22 18.93,59.22 19.18,58.97 28.14,58.97 28.68,59.51 33.12,59.51 33.63,59 49.65,59 50.45,59.8 60.74,59.8 60.8,59.86 61.74,59.86 62.15,59.45 62.15,58.87 v4(62.54,58.48)
  BOTTOM w0.139: J4.107 v13(17.28,37.91)
NFP_PCIE0_PER3_N: length 87.1
  04_SIG w0.11: v6(16.01,35.37) 16.01,35.78 16.13,35.9 17.62,35.9 18.05,36.33 18.05,36.85 18.31,37.11 19.04,37.11 19.29,37.36 19.29,47.14 18.91,47.52 10.78,47.52 10.44,47.86 10.44,50.53 10.36,50.61 10.36,55.86 10.71,56.21 10.86,56.21 11.45,55.63 11.78,55.63 12.09,55.94 12.09,56.28 11.51,56.86 11.51,57.01 11.71,57.22 14.29,57.22 14.62,57.54 14.88,57.87 15.57,58.55 16.46,58.55 16.72,58.3 17.15,57.86 23.93,57.86 24.11,58.05 28.52,58.05 29.06,58.59 32.73,58.59 33.27,58.05 50.01,58.05 50.91,58.95 59.87,58.95 59.95,58.87 59.95,58.6 59.83,58.48 v4(59.55,58.48)
  BOTTOM w0.139: J4.132 v6(16.01,35.37)
NFP_PCIE0_PER3_P: length 87.1
  04_SIG w0.11: v4(60.57,58.48) 60.16,58.88 60.16,58.97 59.97,59.16 50.83,59.16 49.92,58.26 33.36,58.26 32.82,58.8 28.98,58.8 28.44,58.26 24.03,58.26 23.84,58.07 17.24,58.07 16.8,58.51 16.55,58.77 15.48,58.77 14.73,58.01 14.46,57.69 14.2,57.43 11.63,57.43 11.3,57.1 11.3,56.77 11.88,56.19 11.88,56.03 11.69,55.84 11.53,55.84 10.95,56.42 10.62,56.42 10.15,55.95 10.15,50.52 10.23,50.44 10.23,47.77 10.69,47.31 18.82,47.31 19.08,47.05 19.08,37.45 18.95,37.32 18.22,37.32 17.84,36.94 17.84,36.42 17.53,36.11 16.54,36.11 v13(16.01,36.64)
  BOTTOM w0.139: J4.124 v13(16.01,36.64)
NFP_PCIE0_PER4_N: length 82.7
  03_SIG w0.11: v6(16.01,45.53) 15.49,46.06 13.29,46.06 12.82,46.53 12.82,47.21 12.62,47.41 8.18,47.41 6,49.59 6,50.45 5.88,50.57 5.18,50.57 4.94,50.82 4.94,51.25 5.18,51.5 5.88,51.5 6,51.62 6,51.88 5.88,52 5.18,52 4.94,52.25 4.94,52.68 5.18,52.93 5.88,52.93 6,53.05 6,53.31 5.88,53.43 5.18,53.43 4.94,53.67 4.94,54.11 5.18,54.35 5.88,54.35 6,54.47 6,58.66 8.25,60.91 17.43,60.91 17.56,60.78 48.64,60.78 48.79,60.94 57.61,60.94 58.6,59.95 v4(58.6,58.48)
  BOTTOM w0.139: J4.68 v6(16.01,45.53)
NFP_PCIE0_PER4_P: length 82.6
  03_SIG w0.11: v13(16.01,46.8) 16.18,46.63 16.18,46.39 16.06,46.27 13.38,46.27 13.03,46.62 13.03,47.3 12.71,47.63 8.26,47.63 6.21,49.68 6.21,50.54 5.97,50.79 5.27,50.79 5.15,50.91 5.15,51.17 5.27,51.29 5.97,51.29 6.21,51.53 6.21,51.97 5.97,52.21 5.27,52.21 5.15,52.33 5.15,52.59 5.27,52.71 5.97,52.71 6.21,52.96 6.21,53.39 5.97,53.64 5.27,53.64 5.15,53.76 5.15,54.02 5.27,54.14 5.97,54.14 6.21,54.39 6.21,58.57 8.33,60.69 17.35,60.69 17.47,60.57 48.72,60.57 48.88,60.73 57.52,60.73 58.39,59.86 58.39,58.93 57.94,58.48 v4(57.65,58.48)
  BOTTOM w0.139: J4.60 v13(16.01,46.8)
NFP_PCIE0_PER5_N: length 80.8
  03_SIG w0.11: v4(55.65,58.48) 56.08,58.82 56.08,59.37 55.28,60.16 49.33,60.16 49.03,59.86 17.17,59.86 17.05,59.98 8.63,59.98 8.48,59.83 8.48,59.66 8.92,59.22 8.92,58.87 8.62,58.56 8.27,58.56 7.83,59.01 7.65,59.01 7.18,58.53 7.18,58.02 7.3,57.9 8.51,57.9 8.75,57.65 8.75,57.22 8.51,56.97 7.3,56.97 7.18,56.85 7.18,54.81 7.75,54.23 7.75,50.85 8.08,50.53 9.81,50.53 10.19,50.91 10.19,52.39 10.51,52.71 11.44,52.71 11.76,52.38 11.76,51.7 12.13,51.33 12.73,51.33 14,50.06 14.45,50.06 14.69,49.83 14.69,49.72 14.8,49.6 15.07,49.6 15.18,49.72 15.18,49.83 15.41,50.06 17.77,50.06 18.11,49.72 18.11,49.01 17.83,48.72 17.4,48.72 17.28,48.6 v6(17.28,48.07)
  BOTTOM w0.139: J4.51 v6(17.28,48.07)
NFP_PCIE0_PER5_P: length 80.9
  03_SIG w0.11: v13(17.28,49.34) 17.28,49.06 17.4,48.94 17.74,48.94 17.9,49.1 17.9,49.63 17.68,49.85 15.5,49.85 15.39,49.74 15.39,49.63 15.16,49.39 14.71,49.39 14.48,49.63 14.48,49.74 14.37,49.85 13.92,49.85 12.65,51.12 12.04,51.12 11.55,51.61 11.55,52.29 11.35,52.49 10.6,52.49 10.4,52.3 10.4,50.82 9.89,50.32 7.99,50.32 7.54,50.76 7.54,54.15 6.97,54.72 6.97,56.94 7.21,57.19 8.42,57.19 8.54,57.31 8.54,57.57 8.42,57.69 7.21,57.69 6.97,57.93 6.97,58.62 7.57,59.22 7.91,59.22 8.36,58.77 8.53,58.77 8.71,58.96 8.71,59.13 8.27,59.57 8.27,59.92 8.54,60.19 17.14,60.19 17.26,60.07 48.94,60.07 49.24,60.37 55.37,60.37 56.29,59.46 56.29,58.82 v4(56.63,58.48)
  BOTTOM w0.139: J4.43 v13(17.28,49.34)
NFP_PCIE0_PER6_N: length 80.9
  03_SIG w0.11: v4(53.64,58.48) 54.03,58.87 54.03,59.14 53.59,59.58 49.89,59.58 49.46,59.14 16.88,59.14 16.76,59.27 12.25,59.27 11.69,58.7 11.69,58.59 11.68,58.58 11.68,58.3 11.3,57.92 10.51,57.92 10.4,57.81 10.4,57.12 10.51,57.01 12.07,57.01 12.31,56.77 12.31,56.33 12.07,56.09 10.51,56.09 10.4,55.98 10.4,55.44 10.16,55.19 9.55,55.19 9.17,55.57 9.17,55.94 9.04,56.07 8.71,56.07 8.58,55.94 8.58,51.55 8.71,51.42 9.3,51.42 9.43,51.55 9.43,54.31 9.81,54.69 10.16,54.69 10.4,54.45 10.4,54.25 10.68,53.98 12.71,53.98 13.03,53.65 13.03,52.88 13.34,52.57 13.34,51.79 13.46,51.67 13.72,51.67 13.97,51.92 13.97,53.5 14.44,53.98 15.25,53.98 15.57,53.65 15.57,52.81 15.69,52.69 17.73,52.69 18.11,52.3 18.11,51.44 17.89,51.22 17.01,51.22 16.97,51.26 16.13,51.26 16.01,51.14 v6(16.01,50.61)
  BOTTOM w0.139: J4.36 v6(16.01,50.61)
NFP_PCIE0_PER6_P: length 80.9
  03_SIG w0.11: v13(16.01,51.88) 16.01,51.6 16.13,51.48 17.06,51.48 17.1,51.44 17.74,51.44 17.9,51.59 17.9,52.21 17.64,52.47 15.61,52.47 15.36,52.72 15.36,53.56 15.16,53.76 14.53,53.76 14.18,53.42 14.18,51.83 13.81,51.46 13.38,51.46 13.13,51.7 13.13,52.48 12.82,52.79 12.82,53.56 12.62,53.76 10.59,53.76 10.19,54.17 10.19,54.36 10.07,54.48 9.89,54.48 9.64,54.23 9.64,51.46 9.39,51.2 8.62,51.2 8.37,51.46 8.37,56.03 8.62,56.28 9.13,56.28 9.39,56.03 9.39,55.66 9.64,55.4 10.07,55.4 10.19,55.52 10.19,56.07 10.42,56.3 11.98,56.3 12.09,56.41 12.09,56.69 11.98,56.8 10.42,56.8 10.19,57.03 10.19,57.9 10.42,58.13 11.22,58.13 11.47,58.39 11.47,58.67 11.48,58.68 11.48,58.79 12.16,59.48 16.84,59.48 16.97,59.36 49.37,59.36 49.8,59.79 53.68,59.79 54.24,59.23 54.24,58.87 v4(54.63,58.48)
  BOTTOM w0.139: J4.28 v13(16.01,51.88)
NFP_PCIE0_PER7_N: length 82.7
  03_SIG w0.11: v6(17.28,53.15) 17.28,53.52 17.51,53.74 19,53.74 19.29,54.04 19.29,55.01 19.08,55.23 13.28,55.23 13.03,55.48 13.03,55.94 13.27,56.19 13.86,56.19 14.1,56.44 14.1,57.01 13.73,57.39 13.03,57.39 12.9,57.52 12.9,57.72 13.03,57.85 14.49,57.85 14.61,57.73 14.61,56.44 14.85,56.19 18.79,56.19 19.1,56.5 19.1,56.88 18.85,57.13 17.6,57.13 17.47,57.26 17.47,57.72 17.56,57.81 18.91,57.81 19.1,58.01 19.1,58.1 19.44,58.43 20.1,58.43 20.22,58.31 20.22,56.4 20.46,56.16 20.9,56.16 21.14,56.4 21.14,58.31 21.26,58.43 22.15,58.43 22.27,58.31 22.27,55.13 22.51,54.89 22.95,54.89 23.19,55.13 23.19,55.76 23.31,55.88 28.57,55.88 28.82,56.13 28.82,56.56 28.57,56.81 23.31,56.81 23.19,56.93 23.19,58.31 23.31,58.43 49.89,58.43 50.41,58.95 51.8,58.95 51.88,58.87 51.88,58.65 51.71,58.48 v4(51.42,58.48)
  BOTTOM w0.139: J4.19 v6(17.28,53.15)
NFP_PCIE0_PER7_P: length 82.7
  03_SIG w0.11: v4(52.57,58.48) 51.88,59.16 50.32,59.16 49.8,58.64 23.22,58.64 22.98,58.4 22.98,56.84 23.22,56.59 28.48,56.59 28.6,56.47 28.6,56.21 28.48,56.09 23.22,56.09 22.98,55.85 22.98,55.22 22.86,55.1 22.6,55.1 22.48,55.22 22.48,58.4 22.23,58.64 21.18,58.64 20.93,58.4 20.93,56.49 20.81,56.37 20.55,56.37 20.43,56.49 20.43,58.4 20.18,58.64 19.35,58.64 18.89,58.18 18.89,58.1 18.82,58.02 17.47,58.02 17.26,57.81 17.26,57.17 17.51,56.92 18.77,56.92 18.89,56.79 18.89,56.59 18.7,56.4 14.94,56.4 14.82,56.52 14.82,57.82 14.57,58.06 12.94,58.06 12.69,57.81 12.69,57.43 12.94,57.17 13.64,57.17 13.89,56.92 13.89,56.52 13.77,56.4 13.19,56.4 12.81,56.03 12.81,55.4 13.2,55.01 18.99,55.01 19.08,54.93 19.08,54.13 18.91,53.96 17.53,53.96 17.28,54.2 v13(17.28,54.42)
  BOTTOM w0.139: J4.11 v13(17.28,54.42)
NFP_PCIE0_PET0_N: length 53.1
  TOP w0.139: v2(62.9,51.28) U1.AG12
  03_SIG w0.106: 62.3,56.27 62.3,51.89 v2(62.9,51.28)
  03_SIG w0.11: v6(19.82,53.15) 20.35,53.68 21.17,53.68 21.66,54.17 29.11,54.17 29.88,53.4 32.07,53.4 34.35,55.68 35.35,55.68 36.13,56.46 36.16,56.46 36.26,56.56 36.63,56.56 37.03,56.96 45.03,56.96 45.54,57.47 50.14,57.47 50.33,57.28 50.81,57.28 51.41,56.69 52.18,56.69 52.55,56.32 53.25,56.32 53.61,56.69 54.2,56.69 54.49,56.4 55.39,56.4 55.68,56.69 56.1,56.69 56.5,56.28 57.33,56.28 57.73,56.69 61.88,56.69 62.3,56.27
  BOTTOM w0.139: J4.17 v6(19.82,53.15)
NFP_PCIE0_PET0_P: length 53.1
  TOP w0.139: v2(62.9,52.28) U1.AH12
  03_SIG w0.106: 62.45,56.42 62.46,56.41 62.46,56.4 62.5,56.36 62.5,52.07 62.61,51.97 62.79,51.97 62.9,52.07 v2(62.9,52.28)
  03_SIG w0.11: 62.45,56.42 61.96,56.9 57.64,56.9 57.24,56.5 56.59,56.5 56.19,56.9 55.59,56.9 55.3,56.61 54.57,56.61 54.28,56.9 53.52,56.9 53.16,56.54 52.63,56.54 52.27,56.9 51.49,56.9 50.9,57.49 50.42,57.49 50.22,57.68 45.45,57.68 44.95,57.17 37.12,57.17 36.94,57.17 36.54,56.77 36.17,56.77 36.11,56.71 36.08,56.71 35.26,55.89 34.26,55.89 31.98,53.61 29.97,53.61 29.2,54.38 21.58,54.38 21.09,53.89 20.35,53.89 v13(19.82,54.42)
  BOTTOM w0.139: J4.9 v13(19.82,54.42)
NFP_PCIE0_PET1_N: length 51.4
  TOP w0.139: v2(61.9,52.28) U1.AH13
  03_SIG w0.106: 41.52,55.68 41.54,55.68 41.54,55.68 46.15,55.68 46.5,56.03 46.5,56.53 46.65,56.68 50.1,56.68 50.7,56.07 51.1,55.68 61.13,55.68 61.3,55.52 61.3,52.89 v2(61.9,52.28)
  03_SIG w0.11: 41.52,55.68 37.01,55.68 36.3,54.96 34.65,54.96 32.24,52.56 28.64,52.56 28.28,52.92 22.57,52.92 20.83,51.18 19.12,51.18 v6(18.55,50.61)
  BOTTOM w0.139: J4.34 v6(18.55,50.61)
NFP_PCIE0_PET1_P: length 51.3
  TOP w0.139: v2(61.9,53.28) U1.AJ13
  03_SIG w0.106: v2(61.9,53.28) 61.9,53.09 61.79,52.98 61.61,52.98 61.5,53.09 61.5,55.6 61.22,55.89 51.19,55.89 50.19,56.89 46.56,56.89 46.3,56.62 46.3,56.12 46.06,55.89 42.01,55.89 41.54,55.89 41.54,55.89 41.52,55.89
  03_SIG w0.11: 41.52,55.89 36.92,55.89 36.21,55.18 34.56,55.18 32.15,52.77 28.73,52.77 28.37,53.13 22.48,53.13 20.74,51.39 19.04,51.39 v13(18.55,51.88)
  BOTTOM w0.139: J4.26 v13(18.55,51.88)
NFP_PCIE0_PET2_N: length 57.3
  TOP w0.139: v2(60.9,51.28) U1.AG14
  04_SIG w0.106: 41.8,56.83 41.82,56.85 41.82,56.85 41.86,56.89 42.04,56.89 42.04,56.89 49.15,56.89 49.5,56.53 49.5,56.12 49.73,55.89 60.71,55.89 61.5,55.09 61.5,51.89 v2(60.9,51.28)
  04_SIG w0.11: 41.8,56.83 41.14,56.17 41.14,56.17 40.88,55.9 37.46,55.9 37.08,56.27 37.08,56.39 36.7,56.77 36.17,56.77 35.31,55.91 33.9,55.91 31.73,53.74 30.11,53.74 29.46,54.38 21.45,54.38 20.43,53.36 20.43,51.71 20.05,51.33 19.4,51.33 19.29,51.33 19.04,51.08 19.04,48.56 19.28,48.32 19.58,48.32 v6(19.82,48.07)
  BOTTOM w0.139: J4.49 v6(19.82,48.07)
NFP_PCIE0_PET2_P: length 57.2
  TOP w0.139: v2(60.9,52.28) U1.AH14
  04_SIG w0.106: v2(60.9,52.28) 60.63,52.02 60.63,51.87 60.74,51.76 61.08,51.76 61.3,51.97 61.3,55.01 60.62,55.68 49.65,55.68 49.3,56.03 49.3,56.45 49.06,56.68 41.95,56.68
  04_SIG w0.11: v13(19.82,49.34) 19.82,48.78 19.58,48.53 19.37,48.53 19.25,48.65 19.25,50.99 19.38,51.12 20.14,51.12 20.65,51.63 20.65,53.28 21.54,54.17 29.37,54.17 30.02,53.52 31.82,53.52 33.99,55.69 35.39,55.69 36.26,56.56 36.62,56.56 36.87,56.3 36.87,56.18 37.37,55.69 40.96,55.69 41.36,56.08 41.36,56.08 41.95,56.68
  BOTTOM w0.139: J4.41 v13(19.82,49.34)
NFP_PCIE0_PET3_N: length 52
  TOP w0.139: v2(59.9,52.28) U1.AH15
  03_SIG w0.106: 41.52,53.68 41.54,53.68 41.54,53.68 44.06,53.68 44.3,53.45 44.3,52.24 44.85,51.68 47.06,51.68 47.3,51.45 47.3,50.89 47.5,50.68 50.29,50.68 52.5,52.9 52.5,53.45 52.73,53.68 57.2,53.68 58.2,52.68 59.6,52.68 59.9,52.38 v2(59.9,52.28)
  03_SIG w0.11: v6(18.55,45.53) 19.07,46.04 20.35,46.04 23.21,48.9 24.39,48.9 24.77,49.28 24.77,49.78 25.98,50.99 33.48,50.99 33.96,51.48 33.96,51.7 34.23,51.98 34.23,52.54 34.72,53.03 36.78,53.03 37.94,54.19 40.43,54.19 40.94,53.68 41.52,53.68
  BOTTOM w0.139: J4.66 v6(18.55,45.53)
NFP_PCIE0_PET3_P: length 52.1
  TOP w0.139: v2(59.9,53.28) U1.AJ15
  03_SIG w0.106: 41.52,53.89 41.54,53.89 41.54,53.89 44.15,53.89 44.5,53.53 44.5,52.32 44.94,51.89 47.15,51.89 47.5,51.53 47.5,50.97 47.59,50.89 50.2,50.89 52.3,52.98 52.3,53.53 52.65,53.89 57.29,53.89 58.29,52.89 59.54,52.89 59.61,52.95 59.79,52.95 59.9,53.06 v2(59.9,53.28)
  03_SIG w0.11: v13(18.55,46.8) 19.1,46.25 20.26,46.25 23.12,49.11 24.3,49.11 24.56,49.37 24.56,49.87 25.9,51.2 33.39,51.2 33.75,51.57 33.75,51.79 34.02,52.07 34.02,52.62 34.64,53.24 36.69,53.24 37.85,54.4 40.52,54.4 41.03,53.89 41.52,53.89
  BOTTOM w0.139: J4.58 v13(18.55,46.8)
NFP_PCIE0_PET4_N: length 52.9
  TOP w0.139: v2(58.9,51.28) U1.AG16
  03_SIG w0.106: v2(58.9,51.28) 59.04,51.43 59.04,51.78 58.94,51.89 58.73,51.89 58.61,52.01 57.73,52.01 57.4,51.68 56.54,51.68 56.3,51.92 56.3,52.45 56.06,52.68 55.73,52.68 55.5,52.45 55.5,52.03 55.15,51.68 54.74,51.68 54.5,51.45 54.5,49.97 54.21,49.68 47.11,49.68 46.11,50.68 43.65,50.68 43.3,51.03 43.3,52.45 43.06,52.68 41.54,52.68 41.54,52.68 41.52,52.68
  03_SIG w0.11: 41.52,52.68 40.76,52.68 40.52,52.92 38.45,52.92 37.29,51.76 35.02,51.76 34.67,51.41 34.67,51.09 33.81,50.23 26.49,50.23 26.04,49.78 26.04,49.28 24.94,48.19 23.69,48.19 21.15,45.66 21.15,43.24 20.9,42.99 v6(19.82,42.99)
  BOTTOM w0.139: J4.81 v6(19.82,42.99)
NFP_PCIE0_PET4_P: length 52.8
  TOP w0.139: v2(58.9,52.28) U1.AH16
  03_SIG w0.106: 41.52,52.89 41.54,52.89 41.54,52.89 43.15,52.89 43.5,52.53 43.5,51.12 43.73,50.89 46.19,50.89 47.19,49.89 54.13,49.89 54.3,50.05 54.3,51.53 54.65,51.89 55.06,51.89 55.3,52.12 55.3,52.53 55.65,52.89 56.15,52.89 56.5,52.53 56.5,52.01 56.62,51.89 57.31,51.89 57.65,52.22 58.84,52.22 v2(58.9,52.28)
  03_SIG w0.11: v13(19.82,44.26) 19.82,43.71 20.34,43.2 20.81,43.2 20.94,43.33 20.94,45.74 23.6,48.4 24.86,48.4 25.83,49.37 25.83,49.87 26.4,50.44 33.72,50.44 34.46,51.18 34.46,51.5 34.93,51.97 37.2,51.97 38.36,53.13 40.61,53.13 40.85,52.89 41.52,52.89
  BOTTOM w0.139: J4.73 v13(19.82,44.26)
NFP_PCIE0_PET5_N: length 51.9
  TOP w0.139: U1.AH17 v2(56.9,52.28)
  04_SIG w0.106: v2(56.9,52.28) 56.3,52.89 56.3,53.45 56.06,53.68 41.54,53.68 41.54,53.68 41.52,53.68
  04_SIG w0.11: v6(19.82,40.45) 20.34,40.96 21.26,40.96 21.81,41.51 21.81,42 20.48,43.33 20.48,47.71 20.54,47.77 20.54,49.36 21.54,50.36 23.7,50.36 24.8,51.46 28.49,51.46 28.81,51.79 32.44,51.79 33.68,53.03 37.03,53.03 38.19,54.19 40.65,54.19 41.16,53.68 41.52,53.68
  BOTTOM w0.139: J4.98 v6(19.82,40.45)
NFP_PCIE0_PET5_P: length 51.9
  TOP w0.139: U1.AJ17 v2(56.9,53.28)
  04_SIG w0.106: 41.52,53.89 41.54,53.89 41.54,53.89 56.15,53.89 56.5,53.53 56.5,53.08 56.6,52.98 56.76,52.98 56.9,53.13 v2(56.9,53.28)
  04_SIG w0.11: 41.52,53.89 41.25,53.89 40.74,54.4 38.11,54.4 36.94,53.24 33.6,53.24 32.36,52 28.73,52 28.4,51.67 24.71,51.67 23.61,50.57 21.45,50.57 20.33,49.45 20.33,47.86 20.27,47.8 20.27,43.25 21.6,41.91 21.6,41.6 21.17,41.17 20.37,41.17 v13(19.82,41.72)
  BOTTOM w0.139: J4.90 v13(19.82,41.72)
NFP_PCIE0_PET6_N: length 50.5
  TOP w0.139: U1.AG18 v2(55.9,51.28)
  03_SIG w0.106: v2(55.9,51.28) 55.61,51.28 55.5,51.18 55.5,48.99 55.19,48.68 45.57,48.68 45.3,48.95 45.3,49.45 45.06,49.68 43.64,49.68 42.3,51.02 42.3,51.45 42.06,51.68 41.82,51.68 41.82,51.67 41.6,51.67 41.52,51.59 41.46,51.59 41.45,51.59 41.43,51.59
  03_SIG w0.11: 41.43,51.59 40.61,51.59 40.43,51.77 38.66,51.77 38.65,51.77 38.5,51.77 35.95,49.22 32.54,49.22 32.35,49.03 29.61,49.03 28.52,47.95 28.01,47.95 26.72,46.65 26.72,46.49 27.28,45.93 27.28,45.6 26.96,45.29 26.63,45.29 26.07,45.84 25.91,45.84 23.69,43.62 23.69,40.24 22.1,38.65 21.34,38.65 21.09,38.4 v6(21.09,37.91)
  BOTTOM w0.139: J4.113 v6(21.09,37.91)
NFP_PCIE0_PET6_P: length 50.7
  TOP w0.139: U1.AH18 v2(55.9,52.28)
  03_SIG w0.106: v2(55.9,52.28) 55.9,51.87 55.3,51.27 55.3,49.08 55.11,48.89 45.65,48.89 45.5,49.04 45.5,49.53 45.15,49.89 43.72,49.89 42.5,51.11 42.5,51.53 42.15,51.89 41.74,51.89 41.73,51.88 41.52,51.88 41.51,51.88 41.51,51.88 41.43,51.8
  03_SIG w0.11: v13(21.09,39.18) 21.41,38.86 22.01,38.86 23.48,40.33 23.48,43.71 25.83,46.06 26.16,46.06 26.72,45.5 26.87,45.5 27.06,45.69 27.06,45.84 26.51,46.4 26.51,46.73 27.93,48.16 28.44,48.16 29.52,49.24 32.27,49.24 32.45,49.43 35.86,49.43 38.42,51.98 38.56,51.98 38.57,51.98 40.52,51.98 40.7,51.8 41.43,51.8
  BOTTOM w0.139: J4.105 v13(21.09,39.18)
NFP_PCIE0_PET7_N: length 56.7
  TOP w0.139: U1.AH19 v2(54.9,52.28)
  04_SIG w0.106: v2(54.9,52.28) 54.5,52.68 51.68,52.68 51.04,52.04 51.04,51.33 50.59,50.88 50.35,50.88 50.15,50.68 46.49,50.68 46.09,51.08 46.09,51.84 45.25,52.68 41.54,52.68 41.54,52.68 41.52,52.68
  04_SIG w0.11: 41.52,52.68 41.14,52.68 40.79,53.03 39.01,53.03 38.95,52.97 38.12,52.97 36.85,51.7 34.52,51.7 33.89,51.07 29.11,51.07 28.78,50.74 25.94,50.74 24.77,49.57 24.77,49.28 24.39,48.9 23.85,48.9 23.66,49.09 21.54,49.09 21.25,48.8 21.25,47.48 21.19,47.42 21.19,43.63 22.53,42.29 22.53,40.81 21.41,39.69 20.98,39.69 20.56,39.27 20.56,36.35 20.11,35.9 19.08,35.9 v6(18.55,35.37)
  BOTTOM w0.139: J4.130 v6(18.55,35.37)
NFP_PCIE0_PET7_P: length 56.7
  TOP w0.139: U1.AJ19 v2(54.9,53.28)
  04_SIG w0.106: 41.52,52.89 41.54,52.89 41.54,52.89 45.34,52.89 46.3,51.93 46.3,51.16 46.57,50.89 50.06,50.89 50.26,51.08 50.27,51.08 50.5,51.08 50.83,51.42 50.83,52.13 51.59,52.89 54.5,52.89 v2(54.9,53.28)
  04_SIG w0.11: v13(18.55,36.64) 19.08,36.11 20.02,36.11 20.35,36.43 20.35,39.36 20.89,39.9 21.32,39.9 22.32,40.9 22.32,42.2 20.98,43.54 20.98,47.5 21.04,47.56 21.04,48.89 21.45,49.3 23.75,49.3 23.93,49.11 24.3,49.11 24.56,49.37 24.56,49.66 25.85,50.95 28.69,50.95 29.02,51.28 33.8,51.28 34.43,51.91 36.76,51.91 38.03,53.18 38.86,53.18 38.92,53.24 40.88,53.24 41.23,52.89 41.52,52.89
  BOTTOM w0.139: J4.122 v13(18.55,36.64)
NFP_PCIE0_RESET_OUT_L: length 13.2
  TOP w0.127: v3(35.93,38.53) 35.56,38.19 35.56,36.93 U2.P6
  07_SIG w0.121: v3(35.93,38.53) 36.33,38.12 37.96,38.12 38.12,37.96 38.78,37.96 38.96,38.13 40.64,38.13 41.26,38.76 43.07,38.76 43.55,38.28 v8(43.9,38.28)
  BOTTOM w0.147: R409.2 45.4,38.43 45.07,38.76 44.38,38.76 v8(43.9,38.28)
NFP_PCIE0_WAKE_L: length 15.6
  TOP w0.147: v4(25.26,57.43) 25.76,56.92 U20.12 ; R368.1 v5(14.47,58.57)
  07_SIG w0.121: v5(14.47,58.57) 16.75,58.57 17.26,58.06 17.71,58.06 18.15,58.5 18.15,58.78 18.45,59.07 18.8,59.07 18.86,59.01 23.68,59.01 v4(25.26,57.43)
  BOTTOM w0.147: R380.1 25.26,56.7 v4(25.26,57.43)
NFP_PGOOD4: length 25
  TOP w0.127: U2.N14 30.68,37.01 30.68,37.24 v3(30.09,37.83)
  TOP w0.132: U1.R28 v2(45.9,38.28)
  TOP w0.147: v3(30.09,37.83) 30.17,37.83 31.1,38.76 31.1,39.52 30.98,39.65 v1(30.98,40.92)
  07_SIG w0.121: v3(30.09,37.83) 30.38,38.12 30.56,38.12 32.21,39.77 36.07,39.77 36.13,39.71 36.49,39.71 36.55,39.77 39.23,39.77 40.28,40.83 44.02,40.83 45.45,39.39 45.45,39.14 45.9,38.69 v2(45.9,38.28)
NFP_REF_CLK_100M_EN: length 31.7
  TOP w0.127: U2.K3 36.9,34.78 35.92,34.78 v3(35.5,34.36)
  TOP w0.147: R268.1 31.32,49.85 v7(31.48,49.68)
  07_SIG w0.121: v3(35.5,34.36) 34.86,34.36 34.47,34.76 30.38,34.76 30.25,34.88 26.34,34.88 24.3,36.92 24.3,37.8 24.88,38.38 26.15,38.38 30.59,42.82 30.59,43.58 31.99,44.98 31.99,49.17 v7(31.48,49.68)
NFP_REF_CLK_156M_EN: length 32.1
  TOP w0.127: v3(39.43,36.7) 38.97,36.24 38.37,36.24 U2.M1
  TOP w0.147: v5(35.55,56.79) 35.67,56.79 35.84,56.96 R269.1
  07_SIG w0.121: v5(40.25,47.9) 38.98,47.9 37.83,49.05 33.26,49.05 v7(32.88,48.66)
  08_SIG w0.121: v5(40.25,47.9) 40.75,47.27 40.75,42.31 39.43,40.99 v3(39.43,36.7) ; v5(35.55,56.79) 35.67,56.67 35.67,55.27 34.4,54 34.4,50.19 v7(32.88,48.66)
NFP_SERDES0_RX0_N: length 63
  TOP w0.099: U1.AG20 v8(53.9,51.28)
  07_SIG w0.096: v8(53.9,51.28) 53.51,51.68 51.55,51.68 50.56,50.68 41.57,50.68 41.54,50.65 41.49,50.65 41.48,50.64 37.38,50.64 36.67,49.93 32.77,49.93 32.52,50.18 31.08,50.18 30.73,49.83 30.73,47.05 28.98,45.3 28.38,45.3 27.03,43.95 26.83,43.95 26.46,43.58 26.46,42.64 25.51,41.69 25.51,40.52 24.77,39.77 23.85,39.77 23.02,38.95 23.02,38.38 22.54,37.89 22.54,36.67 22.27,36.41 22.27,35.14 20.47,33.33 19.71,33.33 19.39,33.01 19.39,30.86 19.04,30.5 15.74,30.5 15.23,31.01 15.23,32.03 15.59,32.39 17.46,32.39 17.72,32.65 17.72,33.01 17.39,33.33 15.25,33.33 v5(14.74,32.83)
  BOTTOM w0.099: J4.149 v5(14.74,32.83)
NFP_SERDES0_RX0_P: length 63
  TOP w0.099: U1.AH20 v2(53.9,52.28)
  07_SIG w0.096: v2(53.9,52.28) 53.51,51.89 51.47,51.89 50.47,50.89 41.57,50.89 41.54,50.91 41.49,50.91 41.48,50.9 37.27,50.9 36.56,50.19 32.88,50.19 32.63,50.44 30.98,50.44 30.47,49.93 30.47,47.16 28.87,45.56 28.28,45.56 26.93,44.21 26.73,44.21 26.2,43.69 26.2,42.75 25.25,41.8 25.25,40.62 24.66,40.04 23.74,40.04 22.76,39.06 22.76,38.49 22.28,38 22.28,36.78 22.01,36.51 22.01,35.24 20.36,33.59 19.61,33.59 19.13,33.12 19.13,30.96 18.93,30.76 15.84,30.76 15.49,31.12 15.49,31.92 15.7,32.13 17.57,32.13 17.98,32.54 17.98,33.12 17.5,33.59 15.25,33.59 v5(14.74,34.1)
  BOTTOM w0.099: J4.141 v5(14.74,34.1)
NFP_SERDES0_TX0_N: length 63.9
  TOP w0.099: U1.AK20 v8(53.9,54.28)
  08_SIG w0.096: v8(53.9,54.28) 53.51,54.68 50.74,54.68 50.51,54.45 50.51,54.03 50.15,53.68 45.99,53.68 45.29,54.37 45.29,56.98 45.27,57 45.27,57.13 44.84,57.56 35.42,57.56 34.92,57.05 34.92,55.92 31.98,52.98 31.65,52.98 30.21,52.98 28.94,54.25 27.42,54.25 26.66,53.5 25.65,53.5 24.83,52.68 24.83,51.29 22.73,49.19 22.73,48.05 20.52,45.84 20.52,42.65 20.02,42.15 14.56,42.15 14.31,41.9 14.31,36.2 13.98,35.87 13.58,35.87 13.47,35.77 v5(13.47,35.37)
  BOTTOM w0.099: J4.134 v5(13.47,35.37)
NFP_SERDES0_TX0_P: length 64
  TOP w0.099: U1.AL20 v2(53.9,55.28)
  08_SIG w0.096: v2(53.9,55.28) 53.51,54.89 50.65,54.89 50.29,54.53 50.29,54.12 50.06,53.89 46.08,53.89 45.51,54.46 45.51,56.98 45.53,57 45.53,57.24 44.95,57.82 35.31,57.82 34.66,57.16 34.66,56.03 31.87,53.24 31.76,53.24 30.32,53.24 29.05,54.51 27.31,54.51 26.56,53.76 25.54,53.76 24.57,52.78 24.57,51.4 22.47,49.3 22.47,48.16 20.26,45.95 20.26,42.76 19.91,42.41 14.46,42.41 14.05,42.01 14.05,36.31 13.87,36.13 13.58,36.13 13.47,36.24 v5(13.47,36.64)
  BOTTOM w0.099: J4.126 v5(13.47,36.64)
NFP_SERDES1_RX0_N: length 55.9
  TOP w0.099: U1.AG24 v8(49.9,51.28)
  07_SIG w0.096: v5(10.93,40.45) 11.42,40.94 13.71,40.94 14.32,41.54 14.32,41.9 15.99,43.57 16.3,43.57 16.7,43.97 16.7,44.43 17.11,44.83 21.17,44.83 21.39,44.61 22.01,44.61 22.23,44.83 22.56,44.83 24.83,47.1 24.83,49.63 26.68,51.48 28,51.48 29.99,53.48 31.84,53.48 33.76,55.4 35.92,55.4 35.95,55.43 36.72,55.43 36.97,55.68 41.07,55.68 41.22,55.83 41.51,56.12 41.51,56.53 42.91,57.93 48.37,57.93 49.27,57.03 49.27,57 49.29,56.98 49.29,51.89 v8(49.9,51.28)
  BOTTOM w0.099: J4.104 v5(10.93,40.45)
NFP_SERDES1_RX0_P: length 56
  TOP w0.099: U1.AH24 v2(49.9,52.28)
  07_SIG w0.096: v2(49.9,52.28) 49.9,52.09 49.79,51.98 49.61,51.98 49.51,52.08 49.51,57.07 49.48,57.09 49.48,57.12 49.46,57.14 49.46,57.2 48.47,58.19 42.8,58.19 41.25,56.64 41.25,56.23 40.96,55.94 36.86,55.94 36.61,55.69 35.84,55.69 35.81,55.66 33.65,55.66 31.73,53.74 29.89,53.74 27.89,51.74 26.57,51.74 24.57,49.74 24.57,47.21 22.45,45.09 22.13,45.09 21.91,44.87 21.5,44.87 21.28,45.09 17,45.09 16.44,44.53 16.44,44.08 16.19,43.83 15.88,43.83 14.06,42 14.06,41.65 13.6,41.2 11.27,41.2 11.04,41.43 v5(11.04,41.72)
  BOTTOM w0.099: J4.96 v5(11.04,41.72)
NFP_SERDES1_RX1_N: length 56.2
  TOP w0.099: U1.AH25 v8(48.9,52.28)
  07_SIG w0.096: v8(48.9,52.28) 48.29,52.89 48.29,56.85 48.27,56.87 48.27,56.91 48.14,57.04 43.02,57.04 42.5,56.52 42.5,56.28 42.51,56.28 42.51,55.03 42.15,54.68 41.54,54.68 41.34,54.88 41.29,54.88 41.24,54.93 37.62,54.93 36.92,54.23 34.97,54.23 34.61,53.87 33.54,53.87 32.13,52.46 30.03,52.46 28.31,50.74 26.99,50.74 26.16,49.9 26.16,46.62 25.72,46.18 25.56,46.18 23.33,43.94 23.33,43.79 21.83,42.29 19.78,42.29 18.41,40.92 18.41,40.56 17.5,39.65 11.93,39.65 11.67,39.39 11.67,38.53 11.86,38.34 12.02,38.34 12.02,38.34 12.14,38.34 12.25,38.45 12.25,38.78 12.33,38.85 12.33,39.06 v5(12.2,39.18)
  BOTTOM w0.099: J4.111 v5(12.2,39.18)
NFP_SERDES1_RX1_P: length 56.1
  TOP w0.099: U1.AJ25 v2(48.9,53.28)
  07_SIG w0.096: v5(12.2,37.91) 12.08,38.03 11.8,38.03 11.41,38.42 11.41,39.5 11.82,39.91 17.39,39.91 18.15,40.66 18.15,41.03 19.67,42.55 21.72,42.55 23.07,43.9 23.07,44.05 25.46,46.44 25.61,46.44 25.9,46.73 25.9,50.01 26.88,51 28.2,51 29.92,52.72 32.03,52.72 33.44,54.13 34.5,54.13 34.86,54.49 36.81,54.49 37.51,55.19 41.24,55.19 41.29,55.14 41.33,55.14 41.38,55.09 41.4,55.09 41.6,54.89 42.06,54.89 42.29,55.12 42.29,56.22 42.24,56.27 42.24,56.63 42.91,57.3 48.25,57.3 48.53,57.02 48.53,56.87 48.51,56.85 48.51,53.21 48.61,53.11 48.79,53.11 48.9,53.21 v2(48.9,53.28)
  BOTTOM w0.099: J4.119 v5(12.2,37.91)
NFP_SERDES1_RX2_N: length 55.6
  TOP w0.099: U1.AG26 v8(47.9,51.28)
  07_SIG w0.096: v5(10.93,36.64) 10.93,36.12 10.66,35.84 9.73,35.84 9.52,36.06 9.52,36.73 9.89,37.1 18.73,37.1 19.25,37.62 19.25,38.86 20,39.61 21.27,39.61 23.95,42.29 23.95,43.36 24.06,43.47 24.06,43.64 25.87,45.44 26.21,45.44 26.21,45.45 26.41,45.45 27.11,46.15 27.11,46.69 27.43,47 27.43,49.67 27.75,49.99 28.62,49.99 30.34,51.71 32.44,51.71 33.71,52.98 36.92,52.98 38.13,54.18 40.7,54.18 40.79,54.09 41.08,53.8 41.26,53.8 41.46,53.6 41.61,53.6 41.69,53.68 47.15,53.68 47.29,53.53 47.29,51.89 v8(47.9,51.28)
  BOTTOM w0.099: J4.128 v5(10.93,36.64)
